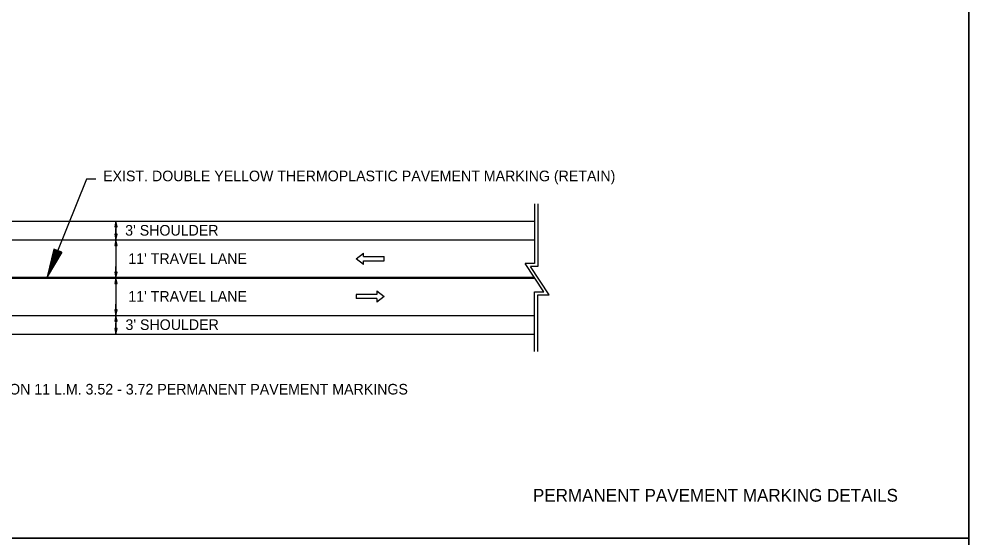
# Model space of a CAD drawing. Extents: x 1372926 to 1373096, y 381240 to 381790.
# Drawn here: x 1372995.2 to 1373096, y 381460.2 to 381515.2 of the extents above; entities that cross this region are included whole.
import ezdxf

# ---------------------------------------------------------------- set-up
doc = ezdxf.new("R2010")
doc.units = 0
for name, color, linetype in [('Default', 7, 'Continuous'), ('DSN_DRFT_Junk-No-Plot', 7, 'Continuous'), ('R_Border Notes', 7, 'Continuous'), ('R_Draft', 7, 'Continuous')]:
    doc.layers.add(name, color=color, linetype=linetype)

msp = doc.modelspace()

# ---------------------------------------------------------------- linework, layer by layer
at = {"layer": 'Default'}
for p, q in [((1373002.37, 381498.21), (1372998.21, 381487.85)), ((1373003.37, 381498.21), (1373002.37, 381498.21)), ((1373049.89, 381495.6), (1373049.89, 381489.26)), ((1373050.23, 381495.6), (1373050.23, 381488.93)), ((1372998.91, 381490.8), (1372998.21, 381487.85)), ((1372999.74, 381490.47), (1372998.21, 381487.85)), ((1372998.98, 381490.78), (1372998.39, 381488.32)), ((1372999.67, 381490.5), (1372998.39, 381488.32)), ((1372999.05, 381490.75), (1372998.59, 381488.8)), ((1372999.6, 381490.52), (1372998.59, 381488.8)), ((1372999.12, 381490.72), (1372998.77, 381489.26)), ((1372999.53, 381490.55), (1372998.77, 381489.26)), ((1372999.74, 381490.47), (1372998.91, 381490.8)), ((1372999.19, 381490.69), (1372998.96, 381489.73)), ((1372999.46, 381490.58), (1372998.96, 381489.73)), ((1372999.26, 381490.66), (1372999.15, 381490.2)), ((1372999.39, 381490.61), (1372999.15, 381490.2)), ((1373030.97, 381489.76), (1373031.75, 381490.36)), ((1373031.75, 381489.99), (1373031.75, 381490.36)), ((1373031.75, 381489.16), (1373030.97, 381489.76)), ((1373031.75, 381489.99), (1373033.95, 381489.99)), ((1373031.75, 381489.54), (1373033.95, 381489.54)), ((1373031.75, 381489.16), (1373031.75, 381489.54)), ((1373033.95, 381489.54), (1373033.95, 381489.99)), ((1373049.89, 381489.26), (1373048.89, 381489.26)), ((1373050.89, 381486.26), (1373048.89, 381489.26)), ((1373051.45, 381485.93), (1373049.45, 381488.93)), ((1373050.23, 381488.93), (1373049.45, 381488.93)), ((1373033.17, 381486.36), (1373033.17, 381485.99)), ((1373033.17, 381486.36), (1373033.95, 381485.76)), ((1373049.89, 381479.93), (1373049.89, 381486.26)), ((1373049.89, 381486.26), (1373050.89, 381486.26)), ((1373033.17, 381485.99), (1373030.97, 381485.99)), ((1373030.97, 381485.99), (1373030.97, 381485.54)), ((1373033.17, 381485.54), (1373030.97, 381485.54)), ((1373033.95, 381485.76), (1373033.17, 381485.16)), ((1373033.17, 381485.54), (1373033.17, 381485.16)), ((1373050.23, 381479.93), (1373050.23, 381485.93)), ((1373050.23, 381485.93), (1373051.45, 381485.93))]:
    msp.add_line(p, q, dxfattribs=at)
for points in [[(1372925.97, 381570.17), (1372925.97, 381460.17), (1373095.97, 381460.17), (1373095.97, 381570.17)], [(1372925.97, 381460.17), (1372925.97, 381350.17), (1373095.97, 381350.17), (1373095.97, 381460.17)]]:
    msp.add_lwpolyline(points, close=True, dxfattribs=at)
at = {"layer": 'DSN_DRFT_Junk-No-Plot'}
msp.add_line((1373005.49, 381493.76), (1373005.49, 381481.76), dxfattribs=at)
for points in [[(1372925.97, 381570.17), (1373095.97, 381570.17), (1373095.97, 381460.17), (1372925.97, 381460.17)], [(1372925.97, 381570.17), (1372925.97, 381460.17), (1373095.97, 381460.17), (1373095.97, 381570.17)], [(1372925.97, 381460.17), (1373095.97, 381460.17), (1373095.97, 381350.17), (1372925.97, 381350.17)], [(1372925.97, 381460.17), (1372925.97, 381350.17), (1373095.97, 381350.17), (1373095.97, 381460.17)]]:
    msp.add_lwpolyline(points, close=True, dxfattribs=at)
for points in [[(1373005.49, 381493.76), (1373005.37, 381493.16), (1373005.61, 381493.16), (1373005.49, 381493.76), (1373005.49, 381492.56)], [(1373005.49, 381491.76), (1373005.61, 381492.36), (1373005.37, 381492.36), (1373005.49, 381491.76), (1373005.49, 381492.96)], [(1373005.49, 381491.76), (1373005.37, 381491.16), (1373005.61, 381491.16), (1373005.49, 381491.76), (1373005.49, 381490.56)], [(1373005.49, 381487.76), (1373005.61, 381488.36), (1373005.37, 381488.36), (1373005.49, 381487.76), (1373005.49, 381488.96)], [(1373005.49, 381487.76), (1373005.37, 381487.16), (1373005.61, 381487.16), (1373005.49, 381487.76), (1373005.49, 381486.56)], [(1373005.49, 381483.76), (1373005.61, 381484.36), (1373005.37, 381484.36), (1373005.49, 381483.76), (1373005.49, 381484.96)], [(1373005.49, 381483.76), (1373005.37, 381483.16), (1373005.61, 381483.16), (1373005.49, 381483.76), (1373005.49, 381482.56)], [(1373005.49, 381481.76), (1373005.61, 381482.36), (1373005.37, 381482.36), (1373005.49, 381481.76), (1373005.49, 381482.96)]]:
    msp.add_lwpolyline(points, dxfattribs=at)
at = {"layer": 'R_Draft'}
for p, q in [((1372973.5, 381493.76), (1373049.89, 381493.76)), ((1372973.5, 381491.76), (1373049.89, 381491.76)), ((1372973.47, 381487.81), (1373049.86, 381487.81)), ((1372973.54, 381487.71), (1373049.93, 381487.71)), ((1372973.5, 381483.76), (1373049.89, 381483.76)), ((1372973.5, 381481.76), (1373049.89, 381481.76))]:
    msp.add_line(p, q, dxfattribs=at)

# ---------------------------------------------------------------- texts
at = {"layer": 'Default'}
msp.add_text('EXIST. DOUBLE YELLOW THERMOPLASTIC PAVEMENT MARKING (RETAIN)', height=1.125, dxfattribs=at).set_placement((1373004.13, 381497.98))
at = {"layer": 'R_Border Notes'}
msp.add_text('PERMANENT PAVEMENT MARKING DETAILS', height=1.35, dxfattribs=at).set_placement((1373049.72, 381464.02))
at = {"layer": 'R_Draft'}
for s, p in [("3' SHOULDER", (1373006.47, 381492.22)), ("11' TRAVEL LANE", (1373006.8, 381489.22)), ("11' TRAVEL LANE", (1373006.8, 381485.22)), ("3' SHOULDER", (1373006.5, 381482.22)), ('HWY. 15 SECTION 11 L.M. 3.52 - 3.72 PERMANENT PAVEMENT MARKINGS', (1372983.29, 381475.38))]:
    msp.add_text(s, height=1.125, dxfattribs=at).set_placement(p)

doc.saveas('drawing.dxf')
